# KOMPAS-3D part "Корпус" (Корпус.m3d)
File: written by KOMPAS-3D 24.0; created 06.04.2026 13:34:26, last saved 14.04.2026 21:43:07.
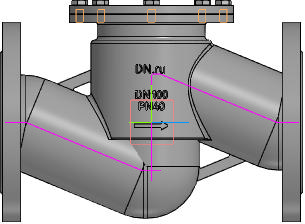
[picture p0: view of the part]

Document properties: Автор: R2D2; Полное имя файла: E:\Работа\Зайцев\VSO3131M-F-S Клапан запорный DN.ru Ду15-100 Ру40\DN100\исходные материалы\Корпус.m3d

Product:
- Body: Труба / Нестандартная труба / L = 181.1 мм  | qty 1
    Материал: Нестандартная труба (density 7856 kg/m3)
    Масса: 50.809346
    Раздел спецификации: Детали
    Примечание: 13,52 кг
    additional columns: Pipeline; 0.11; 0; 0; 0.002; 0.18105; true; 0.04
- Body: Труба / Нестандартная труба / L = 234.8 мм  | qty 1
    Материал: Нестандартная труба (density 7856 kg/m3)
    Масса: 50.809346
    Раздел спецификации: Детали
    Примечание: 17,53 кг
    additional columns: Pipeline; 0.11; 0; 0; 0.002; 0.23484; true; 0.04
- Body: Тело 4  | qty 1
    Материал: Нестандартная труба (density 7856 kg/m3)
    Масса: 50.809346
- Body: Тело 5  | qty 1
    Материал: Нестандартная труба (density 7856 kg/m3)
    Масса: 50.809346
- Body: Тело 8  | qty 1
    Материал: Нестандартная труба (density 7856 kg/m3)
    Масса: 50.809346
- Body: Тело 9  | qty 1
    Материал: Нестандартная труба (density 7856 kg/m3)
    Масса: 50.809346
- Component [standard]: Hexagon head screw ISO 4017 - М10 x 20  | qty 8  | Масса: 0.023019; Рассекать на разрезах: no; source file: C:\Program Files\ASCON\KOMPAS-3D v24\Libs\PolynomLib\DATA\vault\Methods\Kompas\3D\PLib_Bolt_1_ISO_1100.m3d
- Part/product: Корпус
    Масса: 6.9

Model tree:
1. Труба
2. Труба:1  (labels: {F703FF30-5BE6-4673-A7F1-8EDA1BE1E2D1}; SHAPEOBJECT3D_ATTR_BUTT; SHAPEOBJECT3D_ATTR_VALID; SHAPEOBJECT3D_ATTR_BUTT_AREA)
     PIPE_R = 7
3. Труба:2  (labels: {F703FF30-5BE6-4673-A7F1-8EDA1BE1E2D1}; SHAPEOBJECT3D_ATTR_BUTT; SHAPEOBJECT3D_ATTR_VALID; SHAPEOBJECT3D_ATTR_BUTT_AREA)
     PIPE_R = 5
4. Колонна
5. Элемент выдавливания:1
     Смещение 1 = -1; Смещение 2 = -5
6. Скругление:17  (with: Ребро.Элемент выдавливания:1)
     Радиус = 1
7. Скругление:18  (with: Ребро.Элемент выдавливания:1)
8. Скругление:24  (with: Ребро.Скругление:18, Ребро.Элемент выдавливания:1)
     Радиус = 2
9. Элемент выдавливания:2
     Расстояние 1 = 6
10. Скругление:19  (with: Ребро.Элемент выдавливания:2)
     Радиус = 2
11. Эскиз:4  (with: Грань.Элемент выдавливания:1)
12. Элемент выдавливания:3
     Расстояние 1 = 20
13. Скругление:21  (with: Ребро.Элемент выдавливания:3)
14. ОТЛИВКА
15. Скругление:6  (with: Грань.Элемент выдавливания:1)
     Радиус = 2
16. Элемент выдавливания:6  (with: Грань.Элемент выдавливания:1)
     Смещение 1 = 4
17. ЛЕЙБЛ
18. Элемент выдавливания:7  (with: Грань.Элемент выдавливания:1)
     Расстояние 1 = 70.992; Смещение 1 = 1
19. Фланец верх  (with: Ребро.Элемент выдавливания:3)
20. Элемент вращения:2
     Угол 1 = 360
21. Эскиз:12  (with: Грань.Элемент вращения:2)
22. Элемент выдавливания:9  (with: Грань.Элемент вращения:2)
     Расстояние 2 = 20
23. Массив по концентрической сетке:1  (with: Элемент выдавливания:9, Эскиз:12, Грань.Элемент вращения:2)  (8 pattern instances)
     Шаг 2 = 360
24. Фланец
25. Элемент вращения:1
     Угол 1 = 360
26. отвертие во фланце  (with: Грань.Элемент вращения:1)
27. Элемент выдавливания:8
28. Массив по концентрической сетке:2  (with: Элемент выдавливания:8, Эскиз:10, Грань.Элемент вращения:1)  (8 pattern instances)
     Шаг 2 = 360
29. Зеркальный массив:1
30. Экземпляр ( 1 )
31. Экземпляр ( 2 )  (with: Элемент вращения:1, Массив по концентрической сетке:2, Экземпляр ( 1 ), Элемент выдавливания:8)
32. Экземпляр ( 3 )  (with: Элемент выдавливания:8)
33. Экземпляр ( 4 )  (with: Элемент выдавливания:8)
34. Экземпляр ( 5 )  (with: Элемент выдавливания:8)
35. Экземпляр ( 6 )  (with: Элемент выдавливания:8)
36. Экземпляр ( 7 )  (with: Элемент выдавливания:8)
37. Экземпляр ( 8 )  (with: Элемент выдавливания:8)
38. Скругление:25  (with: Ребро.Элемент вращения:2)
     Радиус = 2
39. Скругление:26  (with: Массив по концентрической сетке:1, Грань.Элемент вращения:2)  (labels: Грань.Элемент выдавливания:9.Экземпляр ( 1, 3 ))  (8 pattern instances)
     Радиус = 2; N 1 = 1; Шаг 1 = 10; Шаг 2 = 360; Номер 1 = 1

Expressions: DS/2+3; D1/2; DN/2; D/2; DS-v977*4; LL/2; D1-v1234*2
Referenced files in C:\Program Files\ASCON\KOMPAS-3D v24\Libs\Pipeline\: StylesTemplate.a3d, TemplateHPH, InsulationStylesTemplate.a3d, Insulation
Referenced files in C:\Program Files\ASCON\KOMPAS-3D v24\Templates\: Констр. чертеж А3 гориз. перв. лист.cdt
Referenced files in E:\Работа\Зайцев\VSO3131M-F-S Клапан запорный DN.ru Ду15-100 Ру40\DN20\исходные материалы\: 
Referenced files in C:\Program Files\ASCON\KOMPAS-3D v24\Libs\PolynomLib\DATA\vault\Methods\Kompas\3D\: PLib_Bolt_1_ISO_1100.m3d
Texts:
  Отводы ГОСТ 17375-2001
  Констр. чертеж А3 гориз. перв. лист.cdt
  BOSimple***PART:c031cb5e-65ec-2f83-1ced-75228c8ad34f***PART:A259_7B16EF33AB1642D2[16;1,5;20;10;-;Undefined]
  GOST 26.020 Pr3
  var3D
  смещение колонны вниз
  LL-10
  DN+10
  Hexagon head screw ISO 4017 - М10 x 20 (1)
  hole1
  hole2
  Труба / Нестандартная труба / L = %s мм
